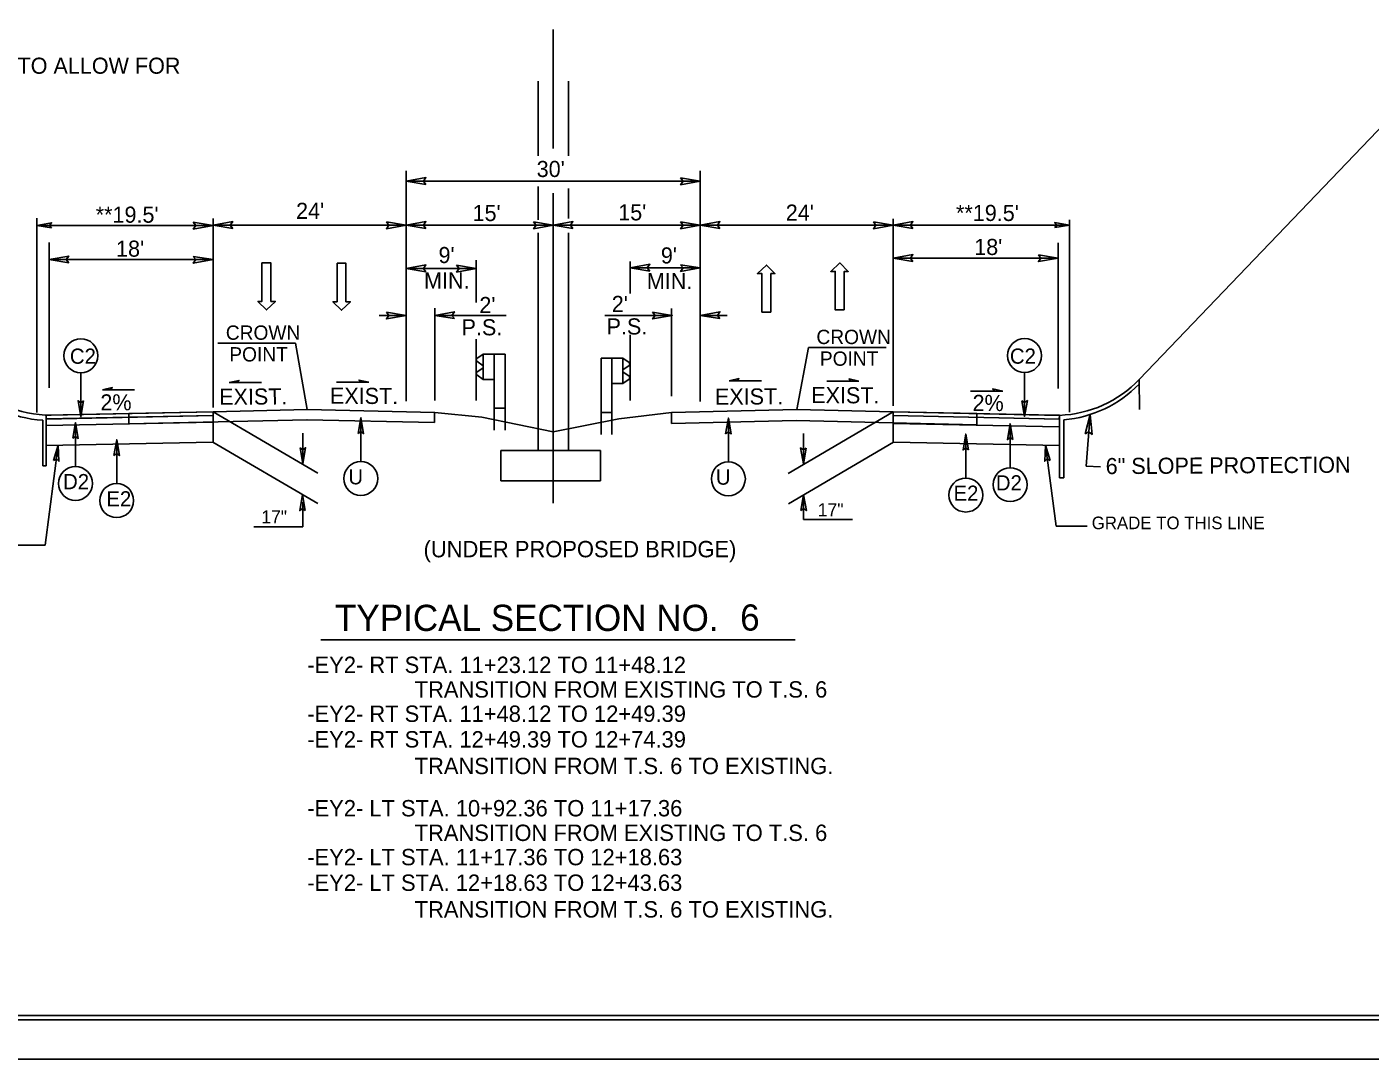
# Model space of a CAD drawing. Extents: x 981824 to 982276, y 44828 to 45204.
# Drawn here: x 982136.8 to 982198.3, y 44914 to 44961.3 of the extents above; entities that cross this region are included whole.
import ezdxf

# ---------------------------------------------------------------- set-up
doc = ezdxf.new("R2010")
doc.units = 0
for name, color, linetype in [('Old_Level_1', 7, 'Continuous'), ('Old_Level_11', 7, 'Continuous'), ('Old_Level_18', 7, 'Continuous'), ('Old_Level_20', 7, 'Continuous'), ('Old_Level_21', 7, 'Continuous'), ('Old_Level_3', 7, 'Continuous'), ('Old_Level_4', 7, 'Continuous'), ('Old_Level_50', 7, 'Continuous'), ('Old_Level_51', 7, 'Continuous'), ('Prop Dimension Text', 7, 'Continuous'), ('Prop Roadway Profile Bench Mark Info Text', 7, 'Continuous'), ('Prop Terminator CELL', 7, 'Continuous'), ('Typical Guardrail CELL', 7, 'Continuous'), ('Typical Terminator CELL', 7, 'Continuous')]:
    doc.layers.add(name, color=color, linetype=linetype)

msp = doc.modelspace()

# ---------------------------------------------------------------- linework, layer by layer
at = {"layer": 'Old_Level_1'}
for p, q in [((982160.931, 44955.677), (982160.931, 44961.129)), ((982160.931, 44939.438), (982160.931, 44953.633)), ((982160.931, 44942.699), (982160.931, 44953.522)), ((982149.666, 44943.726), (982149.132, 44946.764)), ((982172.08, 44943.722), (982172.615, 44946.567)), ((982137.721, 44942.082), (982137.72, 44943.469)), ((982145.353, 44943.154), (982137.72, 44942.992)), ((982145.357, 44943.627), (982137.735, 44943.465)), ((982145.356, 44943.449), (982137.735, 44943.288)), ((982145.355, 44942.235), (982145.357, 44943.627)), ((982145.357, 44943.627), (982150.162, 44940.806)), ((982176.496, 44943.62), (982171.691, 44940.799)), ((982176.496, 44942.233), (982176.495, 44943.62)), ((982176.496, 44943.62), (982184.106, 44943.459)), ((982176.496, 44943.448), (982184.106, 44943.287)), ((982176.499, 44943.092), (982184.093, 44942.931)), ((982184.106, 44942.08), (982184.106, 44943.287)), ((982149.465, 44942.639), (982149.465, 44941.25)), ((982160.242, 44941.854), (982160.242, 44942.942)), ((982161.631, 44941.854), (982161.631, 44942.939)), ((982172.388, 44942.632), (982172.388, 44941.243)), ((982137.674, 44937.513), (982138.264, 44942.093)), ((982145.348, 44942.235), (982137.721, 44942.082)), ((982145.348, 44942.235), (982150.154, 44939.415)), ((982158.536, 44941.854), (982158.536, 44940.462)), ((982158.536, 44941.854), (982159.5, 44941.854)), ((982162.125, 44941.854), (982159.5, 44941.854)), ((982163.09, 44941.854), (982162.125, 44941.854)), ((982162.125, 44941.854), (982162.125, 44941.854)), ((982163.09, 44941.854), (982163.09, 44940.462)), ((982176.505, 44942.232), (982171.699, 44939.412)), ((982176.505, 44942.232), (982184.106, 44942.08)), ((982183.952, 44938.383), (982183.474, 44942.093)), ((982160.871, 44940.462), (982158.536, 44940.462)), ((982160.871, 44940.462), (982163.09, 44940.462)), ((982149.464, 44939.478), (982149.464, 44938.35)), ((982172.396, 44939.821), (982172.396, 44938.693)), ((982147.219, 44938.35), (982149.464, 44938.35)), ((982174.641, 44938.693), (982172.396, 44938.693)), ((982185.371, 44938.383), (982183.952, 44938.383)), ((982136.255, 44937.513), (982137.674, 44937.513))]:
    msp.add_line(p, q, dxfattribs=at)
at = {"layer": 'Old_Level_11'}
for p, q in [((982160.242, 44955.346), (982160.242, 44958.762)), ((982161.631, 44955.346), (982161.631, 44958.762)), ((982187.764, 44945.108), (982200.941, 44958.877)), ((982154.199, 44944.109), (982154.199, 44954.666)), ((982154.199, 44954.189), (982160.931, 44954.189)), ((982160.931, 44954.189), (982167.663, 44954.189)), ((982167.663, 44944.092), (982167.663, 44954.659)), ((982160.242, 44952.417), (982160.242, 44953.944)), ((982161.631, 44952.485), (982161.631, 44953.852)), ((982137.285, 44943.596), (982137.285, 44952.5)), ((982145.357, 44943.818), (982145.357, 44952.471)), ((982176.496, 44943.891), (982176.496, 44952.455)), ((982184.568, 44943.601), (982184.568, 44952.41)), ((982137.285, 44952.16), (982145.357, 44952.16)), ((982145.357, 44952.171), (982154.199, 44952.171)), ((982154.199, 44952.171), (982160.931, 44952.171)), ((982160.242, 44942.942), (982160.242, 44951.822)), ((982160.931, 44952.171), (982167.663, 44952.171)), ((982161.631, 44942.939), (982161.631, 44951.822)), ((982176.496, 44952.171), (982167.663, 44952.171)), ((982176.496, 44952.171), (982184.568, 44952.171)), ((982137.852, 44944.72), (982137.852, 44951.385)), ((982184.049, 44944.686), (982184.049, 44951.357)), ((982137.852, 44950.594), (982145.357, 44950.594)), ((982157.409, 44948.629), (982157.409, 44950.568)), ((982164.453, 44949.037), (982164.453, 44950.51)), ((982176.496, 44950.666), (982184.049, 44950.666)), ((982154.199, 44950.189), (982156.855, 44950.189)), ((982154.199, 44950.189), (982157.409, 44950.189)), ((982164.453, 44950.215), (982167.663, 44950.215)), ((982152.965, 44948.042), (982154.199, 44948.042)), ((982155.504, 44944.135), (982155.504, 44948.374)), ((982155.504, 44948.042), (982158.774, 44948.042)), ((982166.379, 44948.042), (982163.291, 44948.042)), ((982166.354, 44944.341), (982166.354, 44948.348)), ((982168.896, 44948.042), (982167.658, 44948.042)), ((982157.409, 44944.135), (982157.409, 44946.946)), ((982164.453, 44944.135), (982164.453, 44947.15)), ((982187.755, 44945.098), (982187.769, 44943.725)), ((982137.561, 44941.151), (982137.559, 44943.234)), ((982137.722, 44941.151), (982137.72, 44943.473)), ((982141.497, 44943.545), (982145.357, 44943.627)), ((982141.497, 44943.545), (982141.497, 44943.068)), ((982155.489, 44943.603), (982155.489, 44943.128)), ((982155.504, 44943.596), (982157.669, 44943.375)), ((982157.669, 44943.375), (982160.931, 44942.699)), ((982163.93, 44943.307), (982160.931, 44942.699)), ((982163.93, 44943.307), (982166.354, 44943.59)), ((982166.354, 44943.59), (982166.354, 44943.092)), ((982180.31, 44943.028), (982176.459, 44943.122)), ((982180.328, 44943.539), (982176.491, 44943.62)), ((982180.328, 44943.539), (982180.328, 44943.027)), ((982184.106, 44940.595), (982184.106, 44943.468)), ((982184.307, 44940.595), (982184.307, 44943.261)), ((982137.561, 44941.151), (982137.722, 44941.151)), ((982184.106, 44940.595), (982184.307, 44940.595))]:
    msp.add_line(p, q, dxfattribs=at)
for points in [[(982155.101, 44954.041), (982154.199, 44954.189), (982155.101, 44954.353), (982154.986, 44954.189)], [(982166.761, 44954.337), (982167.663, 44954.189), (982166.761, 44954.025), (982166.876, 44954.189)], [(982137.961, 44952.049), (982137.285, 44952.16), (982137.961, 44952.283), (982137.875, 44952.16)], [(982144.454, 44952.307), (982145.357, 44952.16), (982144.454, 44951.996), (982144.569, 44952.16)], [(982146.259, 44952.024), (982145.357, 44952.171), (982146.259, 44952.335), (982146.144, 44952.171)], [(982153.297, 44952.319), (982154.199, 44952.171), (982153.297, 44952.007), (982153.411, 44952.171)], [(982155.101, 44952.024), (982154.199, 44952.171), (982155.101, 44952.335), (982154.986, 44952.171)], [(982160.029, 44952.319), (982160.931, 44952.171), (982160.029, 44952.007), (982160.143, 44952.171)], [(982161.833, 44952.024), (982160.931, 44952.171), (982161.833, 44952.335), (982161.718, 44952.171)], [(982166.761, 44952.319), (982167.663, 44952.171), (982166.761, 44952.007), (982166.876, 44952.171)], [(982168.565, 44952.024), (982167.663, 44952.171), (982168.565, 44952.335), (982168.45, 44952.171)], [(982175.594, 44952.319), (982176.496, 44952.171), (982175.594, 44952.007), (982175.709, 44952.171)], [(982177.399, 44952.024), (982176.496, 44952.171), (982177.399, 44952.335), (982177.284, 44952.171)], [(982183.892, 44952.061), (982184.568, 44952.171), (982183.892, 44952.294), (982183.978, 44952.171)], [(982138.754, 44950.446), (982137.852, 44950.594), (982138.754, 44950.758), (982138.639, 44950.594)], [(982144.454, 44950.742), (982145.357, 44950.594), (982144.454, 44950.43), (982144.569, 44950.594)], [(982155.101, 44950.042), (982154.199, 44950.189), (982155.101, 44950.353), (982154.986, 44950.189)], [(982156.507, 44950.337), (982157.409, 44950.189), (982156.507, 44950.025), (982156.622, 44950.189)], [(982165.355, 44950.067), (982164.453, 44950.215), (982165.355, 44950.379), (982165.24, 44950.215)], [(982166.761, 44950.362), (982167.663, 44950.215), (982166.761, 44950.051), (982166.876, 44950.215)], [(982153.297, 44948.19), (982154.199, 44948.042), (982153.297, 44947.878), (982153.411, 44948.042)], [(982156.406, 44947.895), (982155.504, 44948.042), (982156.406, 44948.206), (982156.291, 44948.042)], [(982165.477, 44948.19), (982166.379, 44948.042), (982165.477, 44947.878), (982165.592, 44948.042)], [(982168.561, 44947.895), (982167.658, 44948.042), (982168.561, 44948.206), (982168.446, 44948.042)], [(982139.428, 44944.127), (982139.304, 44943.407), (982139.176, 44944.131), (982139.304, 44944.039)], [(982182.389, 44944.13), (982182.513, 44943.41), (982182.641, 44944.134), (982182.513, 44944.042)], [(982138.934, 44942.408), (982139.058, 44943.128), (982139.186, 44942.404), (982139.058, 44942.496)], [(982152, 44942.633), (982152.124, 44943.353), (982152.252, 44942.629), (982152.124, 44942.721)], [(982168.826, 44942.617), (982168.95, 44943.337), (982169.078, 44942.613), (982168.95, 44942.705)], [(982181.976, 44942.353), (982181.852, 44943.073), (982181.724, 44942.349), (982181.852, 44942.441)], [(982179.945, 44941.879), (982179.821, 44942.599), (982179.693, 44941.875), (982179.821, 44941.967)], [(982140.821, 44941.621), (982140.945, 44942.341), (982141.073, 44941.617), (982140.945, 44941.709)]]:
    msp.add_lwpolyline(points, close=True, dxfattribs=at)
for points in [[(982145.357, 44943.627), (982149.666, 44943.726)], [(982155.504, 44943.596), (982149.666, 44943.726)], [(982166.354, 44943.59), (982172.08, 44943.722)], [(982176.491, 44943.62), (982172.08, 44943.722)], [(982141.497, 44943.068), (982149.677, 44943.257)], [(982155.489, 44943.128), (982149.656, 44943.258)], [(982166.354, 44943.092), (982172.048, 44943.224)], [(982176.459, 44943.122), (982172.048, 44943.224)]]:
    msp.add_lwpolyline(points, dxfattribs=at)
for centre, radius, start, end in [((982137.941, 44948.8), 5.58, 223.74207, 266.07811), ((982137.941, 44948.8), 5.331, 223.74207, 270), ((982183.907, 44948.791), 5.334, 272.14013, 316.3192), ((982183.897, 44948.579), 5.334, 274.40807, 316.3192)]:
    msp.add_arc(centre, radius, start, end, dxfattribs=at)
at = {"layer": 'Old_Level_18'}
msp.add_lwpolyline([(982227.72, 44999.969), (982107.72, 44999.969), (982107.72, 44915.969), (982227.72, 44915.969)], close=True, dxfattribs=at)
at = {"layer": 'Old_Level_21'}
for p, q in [((982137.72, 44943.469), (982137.72, 44943.469)), ((982145.356, 44943.449), (982137.724, 44943.297)), ((982141.497, 44943.545), (982141.497, 44943.373))]:
    msp.add_line(p, q, dxfattribs=at)
for points in [[(982137.724, 44943.297), (982137.72, 44943.473), (982137.941, 44943.469), (982145.357, 44943.627), (982145.356, 44943.449)], [(982184.102, 44943.291), (982184.106, 44943.468), (982183.885, 44943.463), (982176.496, 44943.62), (982176.496, 44943.448)]]:
    msp.add_lwpolyline(points, close=True, dxfattribs=at)
at = {"layer": 'Old_Level_3'}
for p, q in [((982145.575, 44946.764), (982149.132, 44946.764)), ((982172.615, 44946.567), (982176.172, 44946.567))]:
    msp.add_line(p, q, dxfattribs=at)
at = {"layer": 'Old_Level_4'}
for p, q in [((982147.574, 44944.96), (982146.097, 44944.96)), ((982151.012, 44944.975), (982152.489, 44944.975)), ((982170.462, 44945.04), (982168.985, 44945.04)), ((982173.455, 44945.03), (982174.931, 44945.03)), ((982141.765, 44944.632), (982140.288, 44944.632)), ((982180.032, 44944.573), (982181.509, 44944.573))]:
    msp.add_line(p, q, dxfattribs=at)
for points in [[(982147.594, 44950.441), (982147.594, 44948.678), (982147.409, 44948.678), (982147.799, 44948.288), (982148.209, 44948.678), (982148.004, 44948.678), (982148.004, 44950.441)], [(982151.032, 44950.425), (982151.032, 44948.662), (982150.848, 44948.662), (982151.237, 44948.272), (982151.648, 44948.662), (982151.443, 44948.662), (982151.443, 44950.425)], [(982174.255, 44948.288), (982174.255, 44950.052), (982174.439, 44950.052), (982174.05, 44950.441), (982173.639, 44950.052), (982173.845, 44950.052), (982173.845, 44948.288)], [(982170.899, 44948.189), (982170.899, 44949.952), (982171.084, 44949.952), (982170.694, 44950.342), (982170.284, 44949.952), (982170.489, 44949.952), (982170.489, 44948.189)], [(982146.097, 44944.96), (982146.548, 44945.062), (982146.466, 44944.96)], [(982152.489, 44944.975), (982152.037, 44945.078), (982152.119, 44944.975)], [(982168.985, 44945.04), (982169.437, 44945.143), (982169.355, 44945.04)], [(982174.931, 44945.03), (982174.48, 44945.133), (982174.562, 44945.03)], [(982140.288, 44944.632), (982140.74, 44944.735), (982140.658, 44944.632)], [(982181.509, 44944.573), (982181.058, 44944.675), (982181.14, 44944.573)]]:
    msp.add_lwpolyline(points, close=True, dxfattribs=at)
at = {"layer": 'Old_Level_50'}
msp.add_lwpolyline([(982228.72, 45000.173), (982095.4, 45000.173), (982095.4, 44915.765), (982228.72, 44915.765)], close=True, dxfattribs=at)
at = {"layer": 'Old_Level_51'}
msp.add_lwpolyline([(982229.08, 45001.969), (982094.36, 45001.969), (982094.36, 44913.969), (982229.08, 44913.969)], close=True, dxfattribs=at)
at = {"layer": 'Prop Dimension Text'}
for p, q in [((982139.304, 44945.416), (982139.304, 44943.407)), ((982182.513, 44945.419), (982182.513, 44943.41)), ((982139.058, 44941.118), (982139.058, 44943.128)), ((982152.124, 44941.343), (982152.124, 44943.353)), ((982168.95, 44941.328), (982168.95, 44943.337)), ((982181.852, 44941.063), (982181.852, 44943.073)), ((982179.821, 44940.589), (982179.821, 44942.599)), ((982140.945, 44940.331), (982140.945, 44942.341))]:
    msp.add_line(p, q, dxfattribs=at)
for centre in [(982139.304, 44946.193), (982182.513, 44946.197), (982152.123, 44940.566), (982168.949, 44940.55), (982139.057, 44940.34), (982179.822, 44939.811), (982181.853, 44940.285), (982140.944, 44939.554)]:
    msp.add_circle(centre, 0.778, dxfattribs=at)
at = {"layer": 'Prop Roadway Profile Bench Mark Info Text'}
msp.add_line((982150.294, 44933.181), (982172.014, 44933.181), dxfattribs=at)
at = {"layer": 'Prop Terminator CELL'}
for points in [[(982177.396, 44950.511), (982176.496, 44950.666), (982177.401, 44950.826), (982177.286, 44950.666)], [(982183.149, 44950.821), (982184.049, 44950.666), (982183.144, 44950.506), (982183.259, 44950.666)], [(982185.289, 44942.615), (982185.511, 44943.501), (982185.602, 44942.587), (982185.451, 44942.713)]]:
    msp.add_lwpolyline(points, close=True, dxfattribs=at)
at = {"layer": 'Typical Guardrail CELL'}
for p, q in [((982157.731, 44946.269), (982157.441, 44946.066)), ((982158.228, 44946.269), (982157.731, 44946.269)), ((982157.731, 44946.269), (982157.731, 44945.109)), ((982158.228, 44946.269), (982158.228, 44943.783)), ((982158.228, 44946.269), (982158.725, 44946.269)), ((982158.725, 44946.269), (982158.725, 44943.783)), ((982157.731, 44945.736), (982157.441, 44945.939)), ((982157.731, 44945.642), (982157.441, 44945.439)), ((982157.731, 44945.689), (982157.731, 44945.736)), ((982157.731, 44945.689), (982157.731, 44945.642)), ((982163.62, 44946.078), (982163.122, 44946.078)), ((982163.122, 44946.078), (982163.122, 44943.592)), ((982163.62, 44946.078), (982163.62, 44943.592)), ((982163.62, 44946.078), (982164.117, 44946.078)), ((982164.117, 44946.078), (982164.117, 44944.918)), ((982164.117, 44946.078), (982164.406, 44945.875)), ((982164.117, 44945.545), (982164.406, 44945.747)), ((982164.117, 44945.498), (982164.117, 44945.545)), ((982164.117, 44945.498), (982164.117, 44945.451)), ((982157.731, 44945.109), (982157.441, 44945.312)), ((982158.228, 44945.109), (982157.731, 44945.109)), ((982163.62, 44944.918), (982164.117, 44944.918)), ((982164.117, 44945.451), (982164.406, 44945.248)), ((982164.117, 44944.918), (982164.406, 44945.121)), ((982158.228, 44943.783), (982158.725, 44943.783)), ((982158.228, 44943.783), (982158.228, 44942.775)), ((982158.725, 44943.783), (982158.725, 44942.775)), ((982163.62, 44943.592), (982163.122, 44943.592)), ((982163.122, 44943.592), (982163.122, 44942.584)), ((982163.62, 44943.592), (982163.62, 44942.584))]:
    msp.add_line(p, q, dxfattribs=at)
msp.add_lwpolyline([(982185.995, 44941.108), (982185.332, 44941.134), (982185.511, 44943.501)], dxfattribs=at)
for centre, start, end in [((982157.485, 44946.002), 125.00297, 235.0112), ((982164.362, 44945.811), 304.9888, 54.99702), ((982157.485, 44945.376), 125.0059, 235.0366), ((982164.362, 44945.184), 304.9634, 54.9941)]:
    msp.add_arc(centre, 0.0776, start, end, dxfattribs=at)
at = {"layer": 'Typical Terminator CELL'}
for points in [[(982138.051, 44941.394), (982138.264, 44942.093), (982138.301, 44941.358), (982138.185, 44941.466)], [(982149.341, 44941.97), (982149.465, 44941.25), (982149.593, 44941.974), (982149.465, 44941.882)], [(982172.512, 44941.963), (982172.388, 44941.243), (982172.26, 44941.967), (982172.388, 44941.875)], [(982183.687, 44941.394), (982183.474, 44942.093), (982183.438, 44941.358), (982183.553, 44941.466)], [(982149.581, 44939.103), (982149.457, 44939.823), (982149.329, 44939.099), (982149.457, 44939.191)], [(982172.272, 44939.101), (982172.396, 44939.821), (982172.524, 44939.097), (982172.396, 44939.189)]]:
    msp.add_lwpolyline(points, close=True, dxfattribs=at)

# ---------------------------------------------------------------- texts
at = {"layer": 'Old_Level_1'}
for p in [(982173.045, 44938.837), (982147.566, 44938.507)]:
    msp.add_text('17"', height=0.6, dxfattribs=at).set_placement(p)
at = {"layer": 'Old_Level_11'}
for s, height, rotation, p in [("30'", 0.7382, 360, (982160.174, 44954.378)), ("**19.5'", 0.7382, 360, (982139.985, 44952.284)), ("24'", 0.7382, 360, (982149.157, 44952.46)), ("15'", 0.7382, 360, (982157.238, 44952.359)), ("15'", 0.7382, 360, (982163.907, 44952.39)), ("24'", 0.7382, 360, (982171.579, 44952.378)), ("**19.5'", 0.7382, 360, (982179.373, 44952.363)), ("18'", 0.7382, 360, (982140.917, 44950.728)), ("9'  ", 0.7382, 360, (982155.68, 44950.435)), ("9' ", 0.7382, 360, (982165.86, 44950.417)), ('MIN.', 0.7382, 360, (982155.017, 44949.266)), ('MIN.', 0.7382, 360, (982165.216, 44949.242)), ("2'", 0.7382, 360, (982157.549, 44948.146)), ("2'", 0.7382, 360, (982163.613, 44948.195)), ('P.S.', 0.7382, 360, (982156.734, 44947.126)), ('P.S.', 0.7382, 360, (982163.374, 44947.165)), ('2%', 0.7382, 0.34377, (982140.201, 44943.683)), ('EXIST.', 0.7382, 0.34377, (982145.637, 44943.942)), ('EXIST.', 0.7382, 359.65623, (982150.706, 44943.993)), ('EXIST.', 0.7382, 0.34377, (982168.335, 44943.945)), ('EXIST.', 0.7382, 359.65623, (982172.74, 44944.023)), ('2%', 0.7382, 359.65623, (982180.128, 44943.663)), ('6" SLOPE PROTECTION', 0.73819, 0.34377, (982186.228, 44940.767))]:
    msp.add_text(s, height=height, rotation=rotation, dxfattribs=at).set_placement(p)
msp.add_text("18'", height=0.7382, dxfattribs=at).set_placement((982180.206, 44950.806))
at = {"layer": 'Old_Level_20'}
for s, p in [('C2', (982138.802, 44945.823)), ('C2', (982181.84, 44945.826)), ('D2', (982138.491, 44940.076)), ('U ', (982151.553, 44940.299)), ('U ', (982168.379, 44940.284)), ('D2', (982181.196, 44940.021)), ('E2', (982140.472, 44939.289)), ('E2', (982179.259, 44939.547))]:
    msp.add_text(s, height=0.696, dxfattribs=at).set_placement(p)
at = {"layer": 'Old_Level_3'}
msp.add_text('**  ADDITIONAL WIDTH TO ALLOW FOR ', height=0.73819, rotation=360, dxfattribs=at).set_placement((982125.382, 44959.108))
for s, height, p in [('GRADE TO THIS LINE', 0.576, (982185.586, 44938.246)), ('TYPICAL SECTION NO.  ', 1.2, (982150.938, 44933.584)), ('6', 1.2, (982169.49, 44933.6))]:
    msp.add_text(s, height=height, dxfattribs=at).set_placement(p)
at = {"layer": 'Prop Dimension Text'}
for s, height, p in [('CROWN', 0.656, (982145.942, 44946.922)), ('CROWN', 0.656, (982172.982, 44946.725)), ('POINT', 0.656, (982146.1, 44945.928)), ('POINT', 0.656, (982173.14, 44945.731)), ('(UNDER PROPOSED BRIDGE)', 0.75, (982154.996, 44936.958)), (' -EY2- RT STA. 11+23.12 TO 11+48.12 ', 0.75, (982149.392, 44931.657)), ('TRANSITION FROM EXISTING TO T.S. 6', 0.75, (982154.588, 44930.531)), (' -EY2- RT STA. 11+48.12 TO 12+49.39 ', 0.75, (982149.392, 44929.418)), (' -EY2- RT STA. 12+49.39 TO 12+74.39 ', 0.75, (982149.392, 44928.245)), ('TRANSITION FROM T.S. 6 TO EXISTING.', 0.75, (982154.588, 44927.025)), (' -EY2- LT STA. 10+92.36 TO 11+17.36 ', 0.75, (982149.392, 44925.089)), ('TRANSITION FROM EXISTING TO T.S. 6', 0.75, (982154.588, 44923.963)), (' -EY2- LT STA. 11+17.36 TO 12+18.63 ', 0.75, (982149.392, 44922.85)), (' -EY2- LT STA. 12+18.63 TO 12+43.63', 0.75, (982149.392, 44921.677)), ('TRANSITION FROM T.S. 6 TO EXISTING.', 0.75, (982154.588, 44920.457))]:
    msp.add_text(s, height=height, dxfattribs=at).set_placement(p)

doc.saveas('drawing.dxf')
